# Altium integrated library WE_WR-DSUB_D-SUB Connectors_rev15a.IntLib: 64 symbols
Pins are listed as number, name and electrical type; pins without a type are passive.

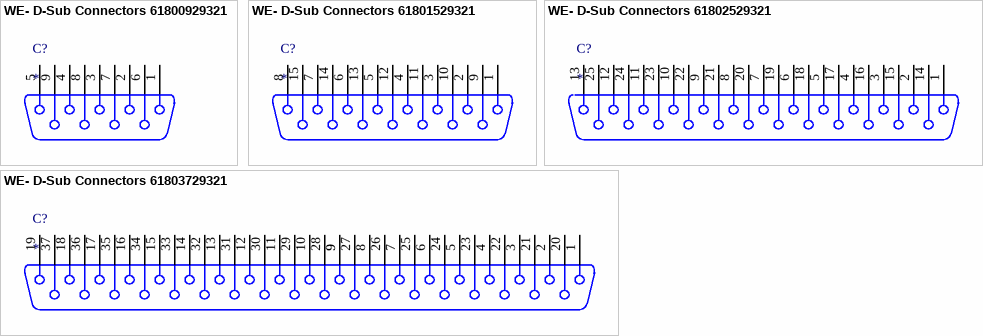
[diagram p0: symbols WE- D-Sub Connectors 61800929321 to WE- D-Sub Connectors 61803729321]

## WE- D-Sub Connectors 61800929321
designator C?
WR-DSUB Female PCB Connector; Manufacturer: Würth Elektronik eiSos GmbH; partNo: 61800929321; ComponentLink1 Description: Manufacturer; ComponentLink2 Description: Datasheet; NoPins: 9
footprint 61800929321
pins: 1, 2, 3, 4, 5, 6, 7, 8, 9

## WE- D-Sub Connectors 61801529321
designator C?
WR-DSUB Female PCB Connector; Manufacturer: Würth Elektronik eiSos GmbH; partNo: 61801529321; ComponentLink1 Description: Manufacturer; ComponentLink2 Description: Datasheet; NoPins: 15
footprint 61801529321
pins: 1, 2, 3, 4, 5, 6, 7, 8, 9, 10, 11, 12, 13, 14, 15

## WE- D-Sub Connectors 61802529321
designator C?
WR-DSUB Female PCB Connector; Manufacturer: Würth Elektronik eiSos GmbH; partNo: 61802529321; ComponentLink1 Description: Manufacturer; ComponentLink2 Description: Datasheet; NoPins: 25
footprint 61802529321
pins: 1, 2, 3, 4, 5, 6, 7, 8, 9, 10, 11, 12, 13, 14, 15, 16, 17, 18, 19, 20, 21, 22, 23, 24, 25

## WE- D-Sub Connectors 61803729321
designator C?
WR-DSUB Female PCB Connector; Manufacturer: Würth Elektronik eiSos GmbH; partNo: 61803729321; ComponentLink1 Description: Manufacturer; ComponentLink2 Description: Datasheet; NoPins: 37
footprint 61803729321
pins: 1, 2, 3, 4, 5, 6, 7, 8, 9, 9, 10, 11, 12, 13, 14, 15, 16, 17, 18, 19, 20, 21, 22, 23, 24, 25, 26, 27, 28, 29, 30, 31, 32, 33, 34, 35, 36, 37


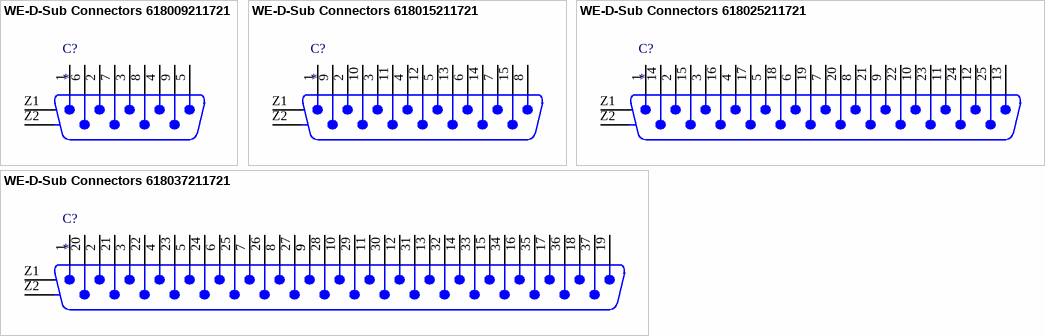
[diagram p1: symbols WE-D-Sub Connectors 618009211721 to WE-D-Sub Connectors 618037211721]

## WE-D-Sub Connectors 618009211721
designator C?
WR-DSUB Male Angled PCB Connector; Manufacturer: Würth Elektronik eiSos GmbH; partNo: 618009211721; ComponentLink1 Description: Manufacturer; ComponentLink2 Description: Datasheet; NoPins: 9
footprint 618009211721
pins: 1, 2, 3, 4, 5, 6, 7, 8, 9, Z1 GND, Z2 GND

## WE-D-Sub Connectors 618015211721
designator C?
WR-DSUB Male Angled PCB Connector; Manufacturer: Würth Elektronik eiSos GmbH; partNo: 618015211721; ComponentLink1 Description: Manufacturer; ComponentLink2 Description: Datasheet; NoPins: 15
footprint 618015211721
pins: 1, 2, 3, 4, 5, 6, 7, 8, 9, 10, 11, 12, 13, 14, 15, Z1 GND, Z2 GND

## WE-D-Sub Connectors 618025211721
designator C?
WR-DSUB Male Angled PCB Connector; Manufacturer: Würth Elektronik eiSos GmbH; partNo: 618025211721; ComponentLink1 Description: Manufacturer; ComponentLink2 Description: Datasheet; NoPins: 25
footprint 618025211721
pins: 1, 2, 3, 4, 5, 6, 7, 8, 9, 10, 11, 12, 13, 14, 15, 16, 17, 18, 19, 20, 21, 22, 23, 24, 25, Z1 GND, Z2 GND

## WE-D-Sub Connectors 618037211721
designator C?
WR-DSUB Male Angled PCB Connector; Manufacturer: Würth Elektronik eiSos GmbH; partNo: 618037211721; ComponentLink1 Description: Manufacturer; ComponentLink2 Description: Datasheet; NoPins: 37
footprint 618037211721
pins: 1, 2, 3, 4, 5, 6, 7, 8, 9, 9, 10, 11, 12, 13, 14, 15, 16, 17, 18, 19, 20, 21, 22, 23, 24, 25, 26, 27, 28, 29, 30, 31, 32, 33, 34, 35, 36, 37, Z1 GND, Z2 GND


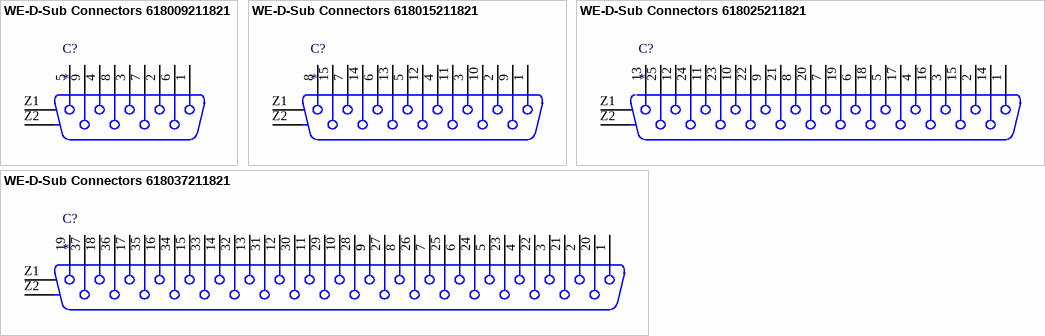
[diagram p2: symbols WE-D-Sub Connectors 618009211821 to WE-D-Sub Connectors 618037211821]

## WE-D-Sub Connectors 618009211821
designator C?
WR-DSUB Female Angled PCB Connector; Manufacturer: Würth Elektronik eiSos GmbH; partNo: 618009211821; ComponentLink1 Description: Manufacturer; ComponentLink2 Description: Datasheet; NoPins: 9
footprint 618009211821
pins: 1, 2, 3, 4, 5, 6, 7, 8, 9, Z1 GND, Z2 GND

## WE-D-Sub Connectors 618015211821
designator C?
WR-DSUB Female Angled PCB Connector; Manufacturer: Würth Elektronik eiSos GmbH; partNo: 618015211821; ComponentLink1 Description: Manufacturer; ComponentLink2 Description: Datasheet; NoPins: 15
footprint 618015211821
pins: 1, 2, 3, 4, 5, 6, 7, 8, 9, 10, 11, 12, 13, 14, 15, Z1 GND, Z2 GND

## WE-D-Sub Connectors 618025211821
designator C?
WR-DSUB Female Angled PCB Connector; Manufacturer: Würth Elektronik eiSos GmbH; partNo: 618025211821; ComponentLink1 Description: Manufacturer; ComponentLink2 Description: Datasheet; NoPins: 25
footprint 618025211821
pins: 1, 2, 3, 4, 5, 6, 7, 8, 9, 10, 11, 12, 13, 14, 15, 16, 17, 18, 19, 20, 21, 22, 23, 24, 25, Z1 GND, Z2 GND

## WE-D-Sub Connectors 618037211821
designator C?
WR-DSUB Female Angled PCB Connector; Manufacturer: Würth Elektronik eiSos GmbH; partNo: 618037211821; ComponentLink1 Description: Manufacturer; ComponentLink2 Description: Datasheet; NoPins: 37
footprint 618037211821
pins: 1, 2, 3, 4, 5, 6, 7, 8, 9, 9, 10, 11, 12, 13, 14, 15, 16, 17, 18, 19, 20, 21, 22, 23, 24, 25, 26, 27, 28, 29, 30, 31, 32, 33, 34, 35, 36, 37, Z1 GND, Z2 GND


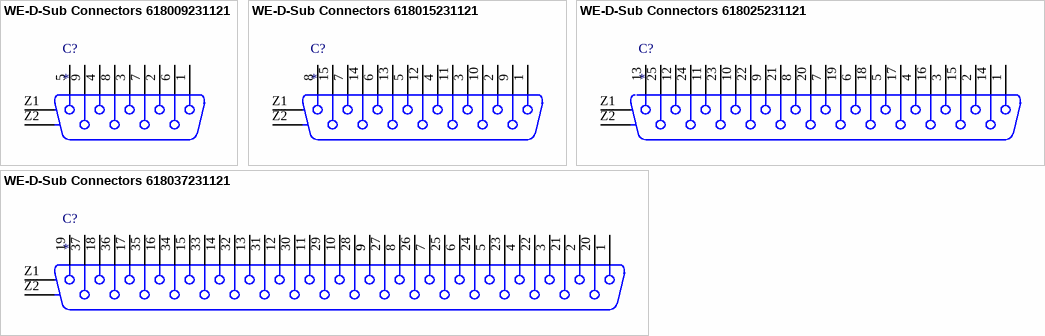
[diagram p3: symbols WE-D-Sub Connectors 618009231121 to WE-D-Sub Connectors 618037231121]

## WE-D-Sub Connectors 618009231121
designator C?
WR-DSUB Female Angled PCB Connector; Manufacturer: Würth Elektronik eiSos GmbH; partNo: 618009231121; ComponentLink1 Description: Manufacturer; ComponentLink2 Description: Datasheet; NoPins: 9
footprint 618009231121
pins: 1, 2, 3, 4, 5, 6, 7, 8, 9, Z1 GND, Z2 GND

## WE-D-Sub Connectors 618015231121
designator C?
WR-DSUB Female Angled PCB Connector; Manufacturer: Würth Elektronik eiSos GmbH; partNo: 618015231121; ComponentLink1 Description: Manufacturer; ComponentLink2 Description: Datasheet; NoPins: 15
footprint 618015231121
pins: 1, 2, 3, 4, 5, 6, 7, 8, 9, 10, 11, 12, 13, 14, 15, Z1 GND, Z2 GND

## WE-D-Sub Connectors 618025231121
designator C?
WR-DSUB Female Angled PCB Connector; Manufacturer: Würth Elektronik eiSos GmbH; partNo: 618025231121; ComponentLink1 Description: Manufacturer; ComponentLink2 Description: Datasheet; NoPins: 25
footprint 618025231121
pins: 1, 2, 3, 4, 5, 6, 7, 8, 9, 10, 11, 12, 13, 14, 15, 16, 17, 18, 19, 20, 21, 22, 23, 24, 25, Z1 GND, Z2 GND

## WE-D-Sub Connectors 618037231121
designator C?
WR-DSUB Female Angled PCB Connector; Manufacturer: Würth Elektronik eiSos GmbH; partNo: 618037231121; ComponentLink1 Description: Manufacturer; ComponentLink2 Description: Datasheet; NoPins: 37
footprint 618037231121
pins: 1, 2, 3, 4, 5, 6, 7, 8, 9, 9, 10, 11, 12, 13, 14, 15, 16, 17, 18, 19, 20, 21, 22, 23, 24, 25, 26, 27, 28, 29, 30, 31, 32, 33, 34, 35, 36, 37, Z1 GND, Z2 GND


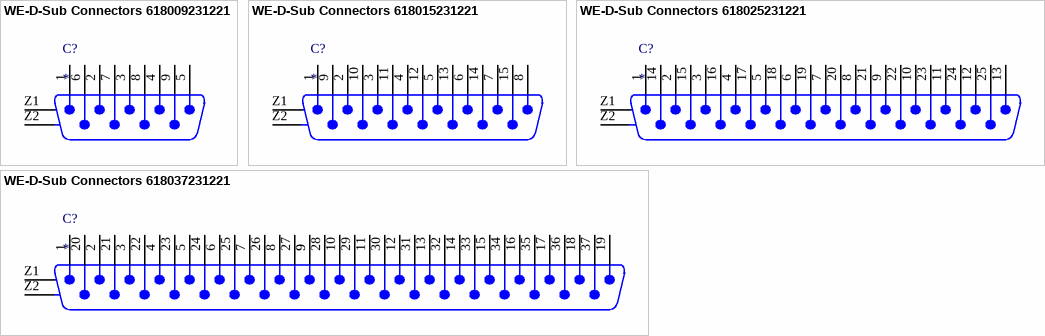
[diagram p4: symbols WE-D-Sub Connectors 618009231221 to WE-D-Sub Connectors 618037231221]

## WE-D-Sub Connectors 618009231221
designator C?
WR-DSUB Male Angled PCB Connector; Manufacturer: Würth Elektronik eiSos GmbH; partNo: 618009231221; ComponentLink1 Description: Manufacturer; ComponentLink2 Description: Datasheet; NoPins: 9
footprint 618009231221
pins: 1, 2, 3, 4, 5, 6, 7, 8, 9, Z1 GND, Z2 GND

## WE-D-Sub Connectors 618015231221
designator C?
WR-DSUB Male Angled PCB Connector; Manufacturer: Würth Elektronik eiSos GmbH; partNo: 618015231221; ComponentLink1 Description: Manufacturer; ComponentLink2 Description: Datasheet; NoPins: 15
footprint 618015231221
pins: 1, 2, 3, 4, 5, 6, 7, 8, 9, 10, 11, 12, 13, 14, 15, Z1 GND, Z2 GND

## WE-D-Sub Connectors 618025231221
designator C?
WR-DSUB Male Angled PCB Connector; Manufacturer: Würth Elektronik eiSos GmbH; partNo: 618025231221; ComponentLink1 Description: Manufacturer; ComponentLink2 Description: Datasheet; NoPins: 25
footprint 618025231221
pins: 1, 2, 3, 4, 5, 6, 7, 8, 9, 10, 11, 12, 13, 14, 15, 16, 17, 18, 19, 20, 21, 22, 23, 24, 25, Z1 GND, Z2 GND

## WE-D-Sub Connectors 618037231221
designator C?
WR-DSUB Male Angled PCB Connector; Manufacturer: Würth Elektronik eiSos GmbH; partNo: 618037231221; ComponentLink1 Description: Manufacturer; ComponentLink2 Description: Datasheet; NoPins: 37
footprint 618037231221
pins: 1, 2, 3, 4, 5, 6, 7, 8, 9, 9, 10, 11, 12, 13, 14, 15, 16, 17, 18, 19, 20, 21, 22, 23, 24, 25, 26, 27, 28, 29, 30, 31, 32, 33, 34, 35, 36, 37, Z1 GND, Z2 GND


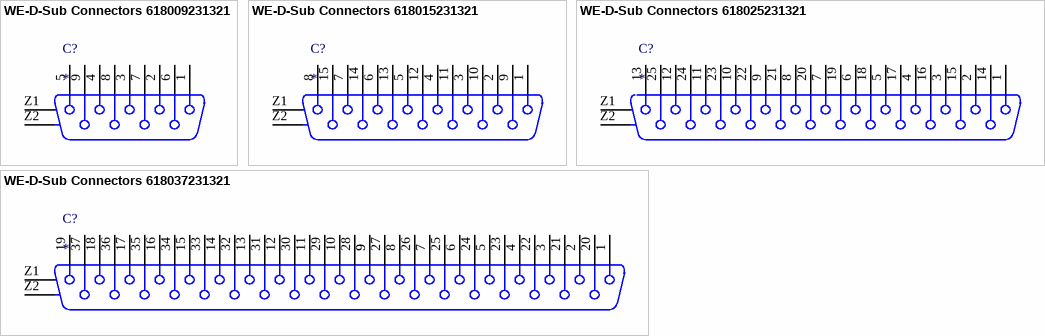
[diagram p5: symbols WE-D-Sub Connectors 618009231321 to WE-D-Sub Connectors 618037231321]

## WE-D-Sub Connectors 618009231321
designator C?
WR-DSUB Female Angled PCB Connector; Manufacturer: Würth Elektronik eiSos GmbH; partNo: 618009231321; ComponentLink1 Description: Manufacturer; ComponentLink2 Description: Datasheet; NoPins: 9
footprint 618009231321
pins: 1, 2, 3, 4, 5, 6, 7, 8, 9, Z1 GND, Z2 GND

## WE-D-Sub Connectors 618015231321
designator C?
WR-DSUB Female Angled PCB Connector; Manufacturer: Würth Elektronik eiSos GmbH; partNo: 618015231321; ComponentLink1 Description: Manufacturer; ComponentLink2 Description: Datasheet; NoPins: 15
footprint 618015231321
pins: 1, 2, 3, 4, 5, 6, 7, 8, 9, 10, 11, 12, 13, 14, 15, Z1 GND, Z2 GND

## WE-D-Sub Connectors 618025231321
designator C?
WR-DSUB Female Angled PCB Connector; Manufacturer: Würth Elektronik eiSos GmbH; partNo: 618025231321; ComponentLink1 Description: Manufacturer; ComponentLink2 Description: Datasheet; NoPins: 25
footprint 618025231321
pins: 1, 2, 3, 4, 5, 6, 7, 8, 9, 10, 11, 12, 13, 14, 15, 16, 17, 18, 19, 20, 21, 22, 23, 24, 25, Z1 GND, Z2 GND

## WE-D-Sub Connectors 618037231321
designator C?
WR-DSUB Female Angled PCB Connector; Manufacturer: Würth Elektronik eiSos GmbH; partNo: 618037231321; ComponentLink1 Description: Manufacturer; ComponentLink2 Description: Datasheet; NoPins: 37
footprint 618037231321
pins: 1, 2, 3, 4, 5, 6, 7, 8, 9, 9, 10, 11, 12, 13, 14, 15, 16, 17, 18, 19, 20, 21, 22, 23, 24, 25, 26, 27, 28, 29, 30, 31, 32, 33, 34, 35, 36, 37, Z1 GND, Z2 GND


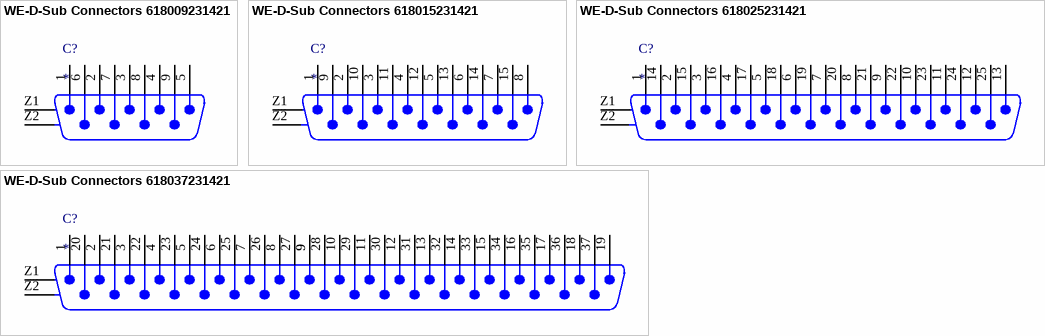
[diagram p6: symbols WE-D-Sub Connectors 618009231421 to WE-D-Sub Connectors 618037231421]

## WE-D-Sub Connectors 618009231421
designator C?
WR-DSUB Male Angled PCB Connector; Manufacturer: Würth Elektronik eiSos GmbH; partNo: 618009231421; ComponentLink1 Description: Manufacturer; ComponentLink2 Description: Datasheet; NoPins: 9
footprint 618009231421
pins: 1, 2, 3, 4, 5, 6, 7, 8, 9, Z1 GND, Z2 GND

## WE-D-Sub Connectors 618015231421
designator C?
WR-DSUB Male Angled PCB Connector; Manufacturer: Würth Elektronik eiSos GmbH; partNo: 618015231421; ComponentLink1 Description: Manufacturer; ComponentLink2 Description: Datasheet; NoPins: 15
footprint 618015231421
pins: 1, 2, 3, 4, 5, 6, 7, 8, 9, 10, 11, 12, 13, 14, 15, Z1 GND, Z2 GND

## WE-D-Sub Connectors 618025231421
designator C?
WR-DSUB Male Angled PCB Connector; Manufacturer: Würth Elektronik eiSos GmbH; partNo: 618025231421; ComponentLink1 Description: Manufacturer; ComponentLink2 Description: Datasheet; NoPins: 25
footprint 618025231421
pins: 1, 2, 3, 4, 5, 6, 7, 8, 9, 10, 11, 12, 13, 14, 15, 16, 17, 18, 19, 20, 21, 22, 23, 24, 25, Z1 GND, Z2 GND

## WE-D-Sub Connectors 618037231421
designator C?
WR-DSUB Male Angled PCB Connector; Manufacturer: Würth Elektronik eiSos GmbH; partNo: 618037231421; ComponentLink1 Description: Manufacturer; ComponentLink2 Description: Datasheet; NoPins: 37
footprint 618037231421
pins: 1, 2, 3, 4, 5, 6, 7, 8, 9, 9, 10, 11, 12, 13, 14, 15, 16, 17, 18, 19, 20, 21, 22, 23, 24, 25, 26, 27, 28, 29, 30, 31, 32, 33, 34, 35, 36, 37, Z1 GND, Z2 GND


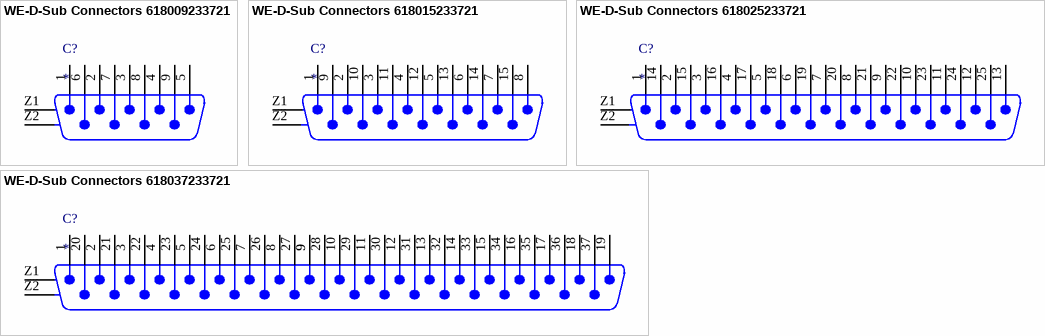
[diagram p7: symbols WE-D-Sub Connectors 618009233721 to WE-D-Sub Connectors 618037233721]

## WE-D-Sub Connectors 618009233721
designator C?
WR-DSUB Male Angled PCB Connector; Manufacturer: Würth Elektronik eiSos GmbH; partNo: 618009233721; ComponentLink1 Description: Manufacturer; ComponentLink2 Description: Datasheet; NoPins: 9
footprint 618009233721
pins: 1, 2, 3, 4, 5, 6, 7, 8, 9, Z1 GND, Z2 GND

## WE-D-Sub Connectors 618015233721
designator C?
WR-DSUB Male Angled PCB Connector; Manufacturer: Würth Elektronik eiSos GmbH; partNo: 618015233721; ComponentLink1 Description: Manufacturer; ComponentLink2 Description: Datasheet; NoPins: 15
footprint 618015233721
pins: 1, 2, 3, 4, 5, 6, 7, 8, 9, 10, 11, 12, 13, 14, 15, Z1 GND, Z2 GND

## WE-D-Sub Connectors 618025233721
designator C?
WR-DSUB Male Angled PCB Connector; Manufacturer: Würth Elektronik eiSos GmbH; partNo: 618025233721; ComponentLink1 Description: Manufacturer; ComponentLink2 Description: Datasheet; NoPins: 25
footprint 618025233721
pins: 1, 2, 3, 4, 5, 6, 7, 8, 9, 10, 11, 12, 13, 14, 15, 16, 17, 18, 19, 20, 21, 22, 23, 24, 25, Z1 GND, Z2 GND

## WE-D-Sub Connectors 618037233721
designator C?
WR-DSUB Male Angled PCB Connector; Manufacturer: Würth Elektronik eiSos GmbH; partNo: 618037233721; ComponentLink1 Description: Manufacturer; ComponentLink2 Description: Datasheet; NoPins: 37
footprint 618037233721
pins: 1, 2, 3, 4, 5, 6, 7, 8, 9, 9, 10, 11, 12, 13, 14, 15, 16, 17, 18, 19, 20, 21, 22, 23, 24, 25, 26, 27, 28, 29, 30, 31, 32, 33, 34, 35, 36, 37, Z1 GND, Z2 GND


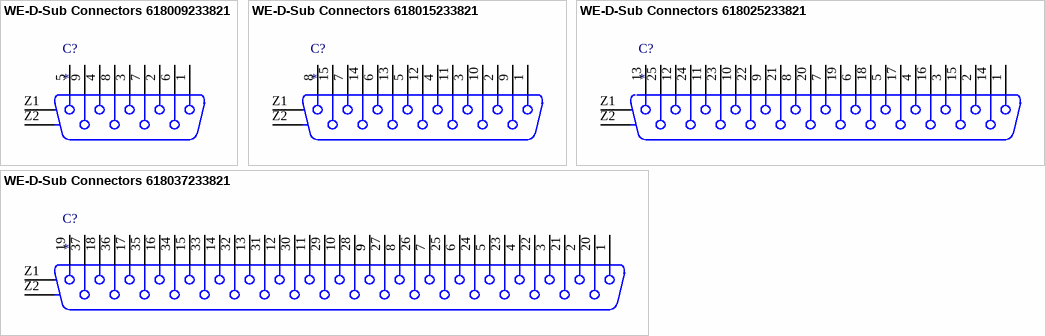
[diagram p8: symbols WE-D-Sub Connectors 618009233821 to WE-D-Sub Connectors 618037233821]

## WE-D-Sub Connectors 618009233821
designator C?
WR-DSUB Female Angled PCB Connector; Manufacturer: Würth Elektronik eiSos GmbH; partNo: 618009233821; ComponentLink1 Description: Manufacturer; ComponentLink2 Description: Datasheet; NoPins: 9
footprint 618009233821
pins: 1, 2, 3, 4, 5, 6, 7, 8, 9, Z1 GND, Z2 GND

## WE-D-Sub Connectors 618015233821
designator C?
WR-DSUB Female Angled PCB Connector; Manufacturer: Würth Elektronik eiSos GmbH; partNo: 618015233821; ComponentLink1 Description: Manufacturer; ComponentLink2 Description: Datasheet; NoPins: 15
footprint 618015233821
pins: 1, 2, 3, 4, 5, 6, 7, 8, 9, 10, 11, 12, 13, 14, 15, Z1 GND, Z2 GND

## WE-D-Sub Connectors 618025233821
designator C?
WR-DSUB Female Angled PCB Connector; Manufacturer: Würth Elektronik eiSos GmbH; partNo: 618025233821; ComponentLink1 Description: Manufacturer; ComponentLink2 Description: Datasheet; NoPins: 25
footprint 618025233821
pins: 1, 2, 3, 4, 5, 6, 7, 8, 9, 10, 11, 12, 13, 14, 15, 16, 17, 18, 19, 20, 21, 22, 23, 24, 25, Z1 GND, Z2 GND

## WE-D-Sub Connectors 618037233821
designator C?
WR-DSUB Female Angled PCB Connector; Manufacturer: Würth Elektronik eiSos GmbH; partNo: 618037233821; ComponentLink1 Description: Manufacturer; ComponentLink2 Description: Datasheet; NoPins: 37
footprint 618037233821
pins: 1, 2, 3, 4, 5, 6, 7, 8, 9, 9, 10, 11, 12, 13, 14, 15, 16, 17, 18, 19, 20, 21, 22, 23, 24, 25, 26, 27, 28, 29, 30, 31, 32, 33, 34, 35, 36, 37, Z1 GND, Z2 GND


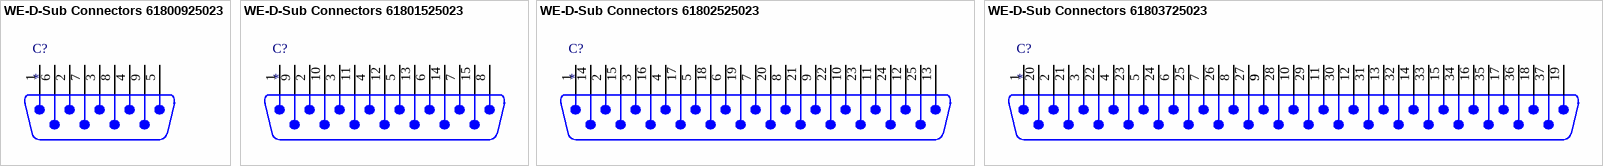
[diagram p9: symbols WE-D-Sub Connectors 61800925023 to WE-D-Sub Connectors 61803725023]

## WE-D-Sub Connectors 61800925023
designator C?
WR-DSUB Male PCB Connector; Manufacturer: Würth Elektronik eiSos GmbH; partNo: 61800925023; ComponentLink1 Description: Manufacturer; ComponentLink2 Description: Datasheet; NoPins: 9
footprint 61800925023
pins: 1, 2, 3, 4, 5, 6, 7, 8, 9

## WE-D-Sub Connectors 61801525023
designator C?
WR-DSUB Male PCB Connector; Manufacturer: Würth Elektronik eiSos GmbH; partNo: 61801525023; ComponentLink1 Description: Manufacturer; ComponentLink2 Description: Datasheet; NoPins: 15
footprint 61801525023
pins: 1, 2, 3, 4, 5, 6, 7, 8, 9, 10, 11, 12, 13, 14, 15

## WE-D-Sub Connectors 61802525023
designator C?
WR-DSUB Male PCB Connector; Manufacturer: Würth Elektronik eiSos GmbH; partNo: 61802525023; ComponentLink1 Description: Manufacturer; ComponentLink2 Description: Datasheet; NoPins: 25
footprint 61802525023
pins: 1, 2, 3, 4, 5, 6, 7, 8, 9, 10, 11, 12, 13, 14, 15, 16, 17, 18, 19, 20, 21, 22, 23, 24, 25

## WE-D-Sub Connectors 61803725023
designator C?
WR-DSUB Male PCB Connector; Manufacturer: Würth Elektronik eiSos GmbH; partNo: 61803725023; ComponentLink1 Description: Manufacturer; ComponentLink2 Description: Datasheet; NoPins: 37
footprint 61803725023
pins: 1, 2, 3, 4, 5, 6, 7, 8, 9, 9, 10, 11, 12, 13, 14, 15, 16, 17, 18, 19, 20, 21, 22, 23, 24, 25, 26, 27, 28, 29, 30, 31, 32, 33, 34, 35, 36, 37


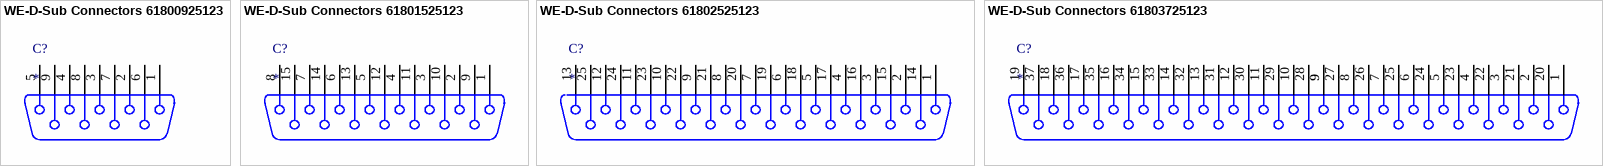
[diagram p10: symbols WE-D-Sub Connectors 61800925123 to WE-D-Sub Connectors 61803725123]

## WE-D-Sub Connectors 61800925123
designator C?
WR-DSUB Female PCB Connector; Manufacturer: Würth Elektronik eiSos GmbH; partNo: 61800925123; ComponentLink1 Description: Manufacturer; ComponentLink2 Description: Datasheet; NoPins: 9
footprint 61800925123 (9 pins, straight)
pins: 1, 2, 3, 4, 5, 6, 7, 8, 9

## WE-D-Sub Connectors 61801525123
designator C?
WR-DSUB Female PCB Connector; Manufacturer: Würth Elektronik eiSos GmbH; partNo: 61801525123; ComponentLink1 Description: Manufacturer; ComponentLink2 Description: Datasheet; NoPins: 15
footprint 61801525123
pins: 1, 2, 3, 4, 5, 6, 7, 8, 9, 10, 11, 12, 13, 14, 15

## WE-D-Sub Connectors 61802525123
designator C?
WR-DSUB Female PCB Connector; Manufacturer: Würth Elektronik eiSos GmbH; partNo: 61802525123; ComponentLink1 Description: Manufacturer; ComponentLink2 Description: Datasheet; NoPins: 25
footprint 61802525123
pins: 1, 2, 3, 4, 5, 6, 7, 8, 9, 10, 11, 12, 13, 14, 15, 16, 17, 18, 19, 20, 21, 22, 23, 24, 25

## WE-D-Sub Connectors 61803725123
designator C?
WR-DSUB Female PCB Connector; Manufacturer: Würth Elektronik eiSos GmbH; partNo: 61803725123; ComponentLink1 Description: Manufacturer; ComponentLink2 Description: Datasheet; NoPins: 37
footprint 61803725123
pins: 1, 2, 3, 4, 5, 6, 7, 8, 9, 9, 10, 11, 12, 13, 14, 15, 16, 17, 18, 19, 20, 21, 22, 23, 24, 25, 26, 27, 28, 29, 30, 31, 32, 33, 34, 35, 36, 37


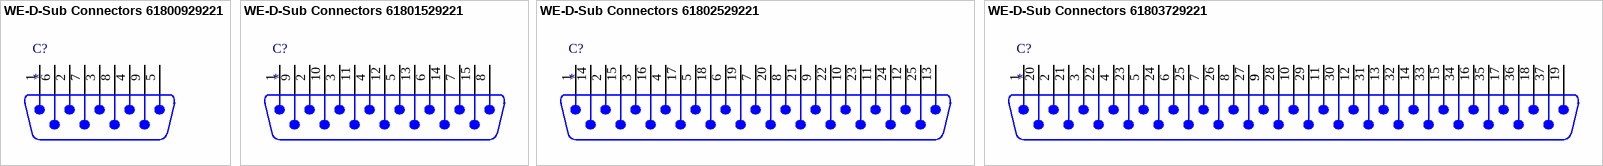
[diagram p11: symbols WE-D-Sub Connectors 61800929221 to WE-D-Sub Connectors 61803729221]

## WE-D-Sub Connectors 61800929221
designator C?
WR-DSUB Male PCB Connector; Manufacturer: Würth Elektronik eiSos GmbH; partNo: 61800929221; ComponentLink1 Description: Manufacturer; ComponentLink2 Description: Datasheet; NoPins: 9
footprint 61800929221
pins: 1, 2, 3, 4, 5, 6, 7, 8, 9

## WE-D-Sub Connectors 61801529221
designator C?
WR-DSUB Male PCB Connector; Manufacturer: Würth Elektronik eiSos GmbH; partNo: 61801529221; ComponentLink1 Description: Manufacturer; ComponentLink2 Description: Datasheet; NoPins: 15
footprint 61801529221
pins: 1, 2, 3, 4, 5, 6, 7, 8, 9, 10, 11, 12, 13, 14, 15

## WE-D-Sub Connectors 61802529221
designator C?
WR-DSUB Male PCB Connector; Manufacturer: Würth Elektronik eiSos GmbH; partNo: 61802529221; ComponentLink1 Description: Manufacturer; ComponentLink2 Description: Datasheet; NoPins: 25
footprint 61802529221
pins: 1, 2, 3, 4, 5, 6, 7, 8, 9, 10, 11, 12, 13, 14, 15, 16, 17, 18, 19, 20, 21, 22, 23, 24, 25

## WE-D-Sub Connectors 61803729221
designator C?
WR-DSUB Male PCB Connector; Manufacturer: Würth Elektronik eiSos GmbH; partNo: 61803729221; ComponentLink1 Description: Manufacturer; ComponentLink2 Description: Datasheet; NoPins: 37
footprint 61803729221
pins: 1, 2, 3, 4, 5, 6, 7, 8, 9, 9, 10, 11, 12, 13, 14, 15, 16, 17, 18, 19, 20, 21, 22, 23, 24, 25, 26, 27, 28, 29, 30, 31, 32, 33, 34, 35, 36, 37


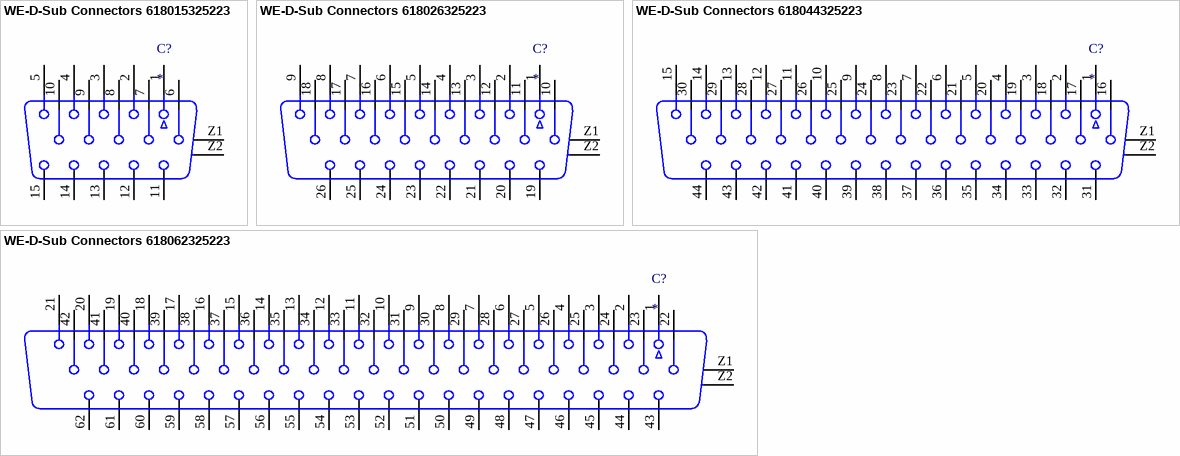
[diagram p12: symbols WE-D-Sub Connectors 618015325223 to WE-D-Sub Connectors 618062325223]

## WE-D-Sub Connectors 618015325223
designator C?
WR-DSUB Female High Density Angled PCB Connector; Manufacturer: Würth Elektronik eiSos GmbH; partNo: 618015325223; ComponentLink1 Description: Manufacturer; ComponentLink2 Description: Datasheet; NoPins: 15
footprint 618015325223
pins: 1, 2, 3, 4, 5, 6, 7, 8, 9, 10, 11, 12, 13, 14, 15, Z1 GND, Z2 GND

## WE-D-Sub Connectors 618026325223
designator C?
WR-DSUB Female High Density Angled PCB Connector; Manufacturer: Würth Elektronik eiSos GmbH; partNo: 618026325223; ComponentLink1 Description: Manufacturer; ComponentLink2 Description: Datasheet; NoPins: 26
footprint 618026325223
pins: 1, 2, 3, 4, 5, 6, 7, 8, 9, 10, 11, 12, 13, 14, 15, 16, 17, 18, 19, 20, 21, 22, 23, 24, 25, 26, Z1 GND, Z2 GND

## WE-D-Sub Connectors 618044325223
designator C?
WR-DSUB Female High Density Angled PCB Connector; Manufacturer: Würth Elektronik eiSos GmbH; partNo: 618044325223; ComponentLink1 Description: Manufacturer; ComponentLink2 Description: Datasheet; NoPins: 44
footprint 618044325223
pins: 1, 2, 3, 4, 5, 6, 7, 8, 9, 10, 11, 12, 13, 14, 15, 16, 17, 18, 19, 20, 21, 22, 23, 24, 25, 26, 27, 28, 29, 30, 31, 32, 33, 34, 35, 36, 37, 38, 39, 40, 41, 42, 43, 44, Z1 GND, Z2 GND

## WE-D-Sub Connectors 618062325223
designator C?
WR-DSUB Female High Density Angled PCB Connector; Manufacturer: Würth Elektronik eiSos GmbH; partNo: 618062325223; ComponentLink1 Description: Manufacturer; ComponentLink2 Description: Datasheet; NoPins: 62
footprint 618062325223
pins: 1, 2, 3, 4, 5, 6, 7, 8, 9, 10, 11, 12, 13, 14, 15, 16, 17, 18, 19, 20, 21, 22, 23, 24, 25, 26, 27, 28, 29, 30, 31, 32, 33, 34, 35, 36, 37, 38, 39, 40, 41, 42, 43, 44, 45, 46, 47, 48, 49, 50, 51, 52, 53, 54, 55, 56, 57, 58, 59, 60, 61, 62, Z1 GND, Z2 GND


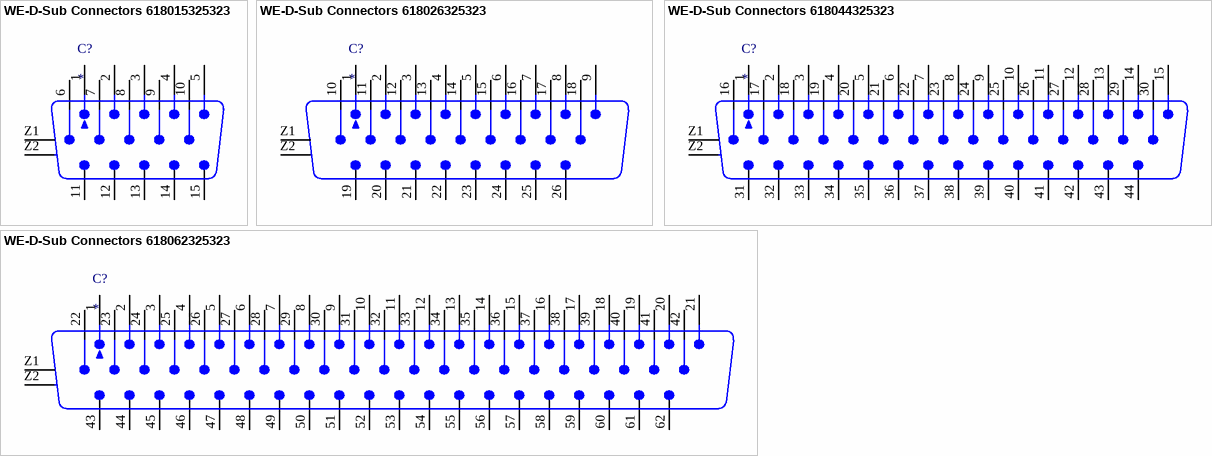
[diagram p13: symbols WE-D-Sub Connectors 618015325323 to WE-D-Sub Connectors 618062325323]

## WE-D-Sub Connectors 618015325323
designator C?
WR-DSUB Male High Density Angled PCB Connector; Manufacturer: Würth Elektronik eiSos GmbH; partNo: 618015325323; ComponentLink1 Description: Manufacturer; ComponentLink2 Description: Datasheet; NoPins: 15
footprint 618015325323
pins: 1, 2, 3, 4, 5, 6, 7, 8, 9, 10, 11, 12, 13, 14, 15, Z1 GND, Z2 GND

## WE-D-Sub Connectors 618026325323
designator C?
WR-DSUB Male High Density Angled PCB Connector; Manufacturer: Würth Elektronik eiSos GmbH; partNo: 618026325323; ComponentLink1 Description: Manufacturer; ComponentLink2 Description: Datasheet; NoPins: 26
footprint 618026325323
pins: 1, 2, 3, 4, 5, 6, 7, 8, 9, 10, 11, 12, 13, 14, 15, 16, 17, 18, 19, 20, 21, 22, 23, 24, 25, 26, Z1 GND, Z2 GND

## WE-D-Sub Connectors 618044325323
designator C?
WR-DSUB Male High Density Angled PCB Connector; Manufacturer: Würth Elektronik eiSos GmbH; partNo: 618044325323; ComponentLink1 Description: Manufacturer; ComponentLink2 Description: Datasheet; NoPins: 44
footprint 618044325323
pins: 1, 2, 3, 4, 5, 6, 7, 8, 9, 10, 11, 12, 13, 14, 15, 16, 17, 18, 19, 20, 21, 22, 23, 24, 25, 26, 27, 28, 29, 30, 31, 32, 33, 34, 35, 36, 37, 38, 39, 40, 41, 42, 43, 44, Z1 GND, Z2 GND

## WE-D-Sub Connectors 618062325323
designator C?
WR-DSUB Male High Density Angled PCB Connector; Manufacturer: Würth Elektronik eiSos GmbH; partNo: 618062325323; ComponentLink1 Description: Manufacturer; ComponentLink2 Description: Datasheet; NoPins: 62
footprint 618062325323
pins: 1, 2, 3, 4, 5, 6, 7, 8, 9, 10, 11, 12, 13, 14, 15, 16, 17, 18, 19, 20, 21, 22, 23, 24, 25, 26, 27, 28, 29, 30, 31, 32, 33, 34, 35, 36, 37, 38, 39, 40, 41, 42, 43, 44, 45, 46, 47, 48, 49, 50, 51, 52, 53, 54, 55, 56, 57, 58, 59, 60, 61, 62, Z1 GND, Z2 GND


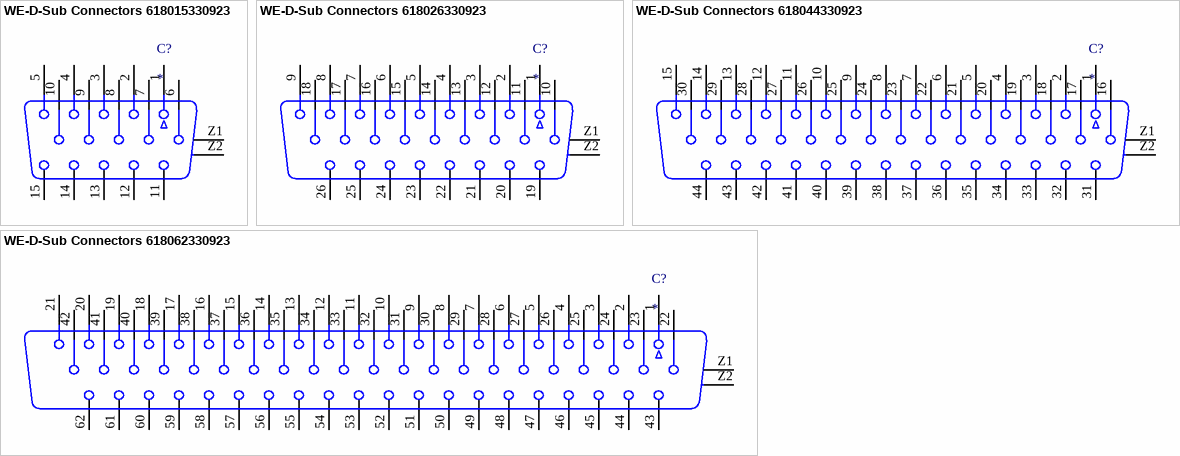
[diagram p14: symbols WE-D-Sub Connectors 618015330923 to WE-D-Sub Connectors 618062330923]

## WE-D-Sub Connectors 618015330923
designator C?
WR-DSUB Female High Density Angled PCB Connector; Manufacturer: Würth Elektronik eiSos GmbH; partNo: 618015330923; ComponentLink1 Description: Manufacturer; ComponentLink2 Description: Datasheet; NoPins: 15
footprint 618015330923
pins: 1, 2, 3, 4, 5, 6, 7, 8, 9, 10, 11, 12, 13, 14, 15, Z1 GND, Z2 GND

## WE-D-Sub Connectors 618026330923
designator C?
WR-DSUB Female High Density Angled PCB Connector; Manufacturer: Würth Elektronik eiSos GmbH; partNo: 618026330923; ComponentLink1 Description: Manufacturer; ComponentLink2 Description: Datasheet; NoPins: 26
footprint 618026330923
pins: 1, 2, 3, 4, 5, 6, 7, 8, 9, 10, 11, 12, 13, 14, 15, 16, 17, 18, 19, 20, 21, 22, 23, 24, 25, 26, Z1 GND, Z2 GND

## WE-D-Sub Connectors 618044330923
designator C?
WR-DSUB Female High Density Angled PCB Connector; Manufacturer: Würth Elektronik eiSos GmbH; partNo: 618044330923; ComponentLink1 Description: Manufacturer; ComponentLink2 Description: Datasheet; NoPins: 44
footprint 618044330923
pins: 1, 2, 3, 4, 5, 6, 7, 8, 9, 10, 11, 12, 13, 14, 15, 16, 17, 18, 19, 20, 21, 22, 23, 24, 25, 26, 27, 28, 29, 30, 31, 32, 33, 34, 35, 36, 37, 38, 39, 40, 41, 42, 43, 44, Z1 GND, Z2 GND

## WE-D-Sub Connectors 618062330923
designator C?
WR-DSUB Female High Density Angled PCB Connector; Manufacturer: Würth Elektronik eiSos GmbH; partNo: 618062330923; ComponentLink1 Description: Manufacturer; ComponentLink2 Description: Datasheet; NoPins: 62
footprint 618062330923
pins: 1, 2, 3, 4, 5, 6, 7, 8, 9, 10, 11, 12, 13, 14, 15, 16, 17, 18, 19, 20, 21, 22, 23, 24, 25, 26, 27, 28, 29, 30, 31, 32, 33, 34, 35, 36, 37, 38, 39, 40, 41, 42, 43, 44, 45, 46, 47, 48, 49, 50, 51, 52, 53, 54, 55, 56, 57, 58, 59, 60, 61, 62, Z1 GND, Z2 GND


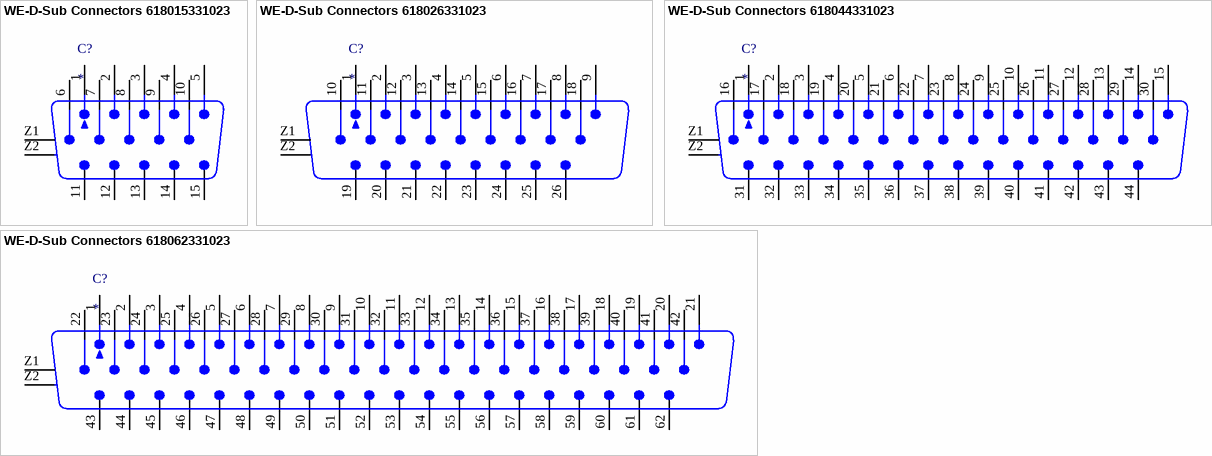
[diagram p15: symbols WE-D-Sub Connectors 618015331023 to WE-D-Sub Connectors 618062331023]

## WE-D-Sub Connectors 618015331023
designator C?
WR-DSUB Male High Density Angled PCB Connector; Manufacturer: Würth Elektronik eiSos GmbH; partNo: 618015331023; ComponentLink1 Description: Manufacturer; ComponentLink2 Description: Datasheet; NoPins: 15
footprint 618015331023
pins: 1, 2, 3, 4, 5, 6, 7, 8, 9, 10, 11, 12, 13, 14, 15, Z1 GND, Z2 GND

## WE-D-Sub Connectors 618026331023
designator C?
WR-DSUB Male High Density Angled PCB Connector; Manufacturer: Würth Elektronik eiSos GmbH; partNo: 618026331023; ComponentLink1 Description: Manufacturer; ComponentLink2 Description: Datasheet; NoPins: 26
footprint 618026331023
pins: 1, 2, 3, 4, 5, 6, 7, 8, 9, 10, 11, 12, 13, 14, 15, 16, 17, 18, 19, 20, 21, 22, 23, 24, 25, 26, Z1 GND, Z2 GND

## WE-D-Sub Connectors 618044331023
designator C?
WR-DSUB Male High Density Angled PCB Connector; Manufacturer: Würth Elektronik eiSos GmbH; partNo: 618044331023; ComponentLink1 Description: Manufacturer; ComponentLink2 Description: Datasheet; NoPins: 44
footprint 618044331023
pins: 1, 2, 3, 4, 5, 6, 7, 8, 9, 10, 11, 12, 13, 14, 15, 16, 17, 18, 19, 20, 21, 22, 23, 24, 25, 26, 27, 28, 29, 30, 31, 32, 33, 34, 35, 36, 37, 38, 39, 40, 41, 42, 43, 44, Z1 GND, Z2 GND

## WE-D-Sub Connectors 618062331023
designator C?
WR-DSUB Male High Density Angled PCB Connector; Manufacturer: Würth Elektronik eiSos GmbH; partNo: 618062331023; ComponentLink1 Description: Manufacturer; ComponentLink2 Description: Datasheet; NoPins: 62
footprint 618062331023
pins: 1, 2, 3, 4, 5, 6, 7, 8, 9, 10, 11, 12, 13, 14, 15, 16, 17, 18, 19, 20, 21, 22, 23, 24, 25, 26, 27, 28, 29, 30, 31, 32, 33, 34, 35, 36, 37, 38, 39, 40, 41, 42, 43, 44, 45, 46, 47, 48, 49, 50, 51, 52, 53, 54, 55, 56, 57, 58, 59, 60, 61, 62, Z1 GND, Z2 GND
